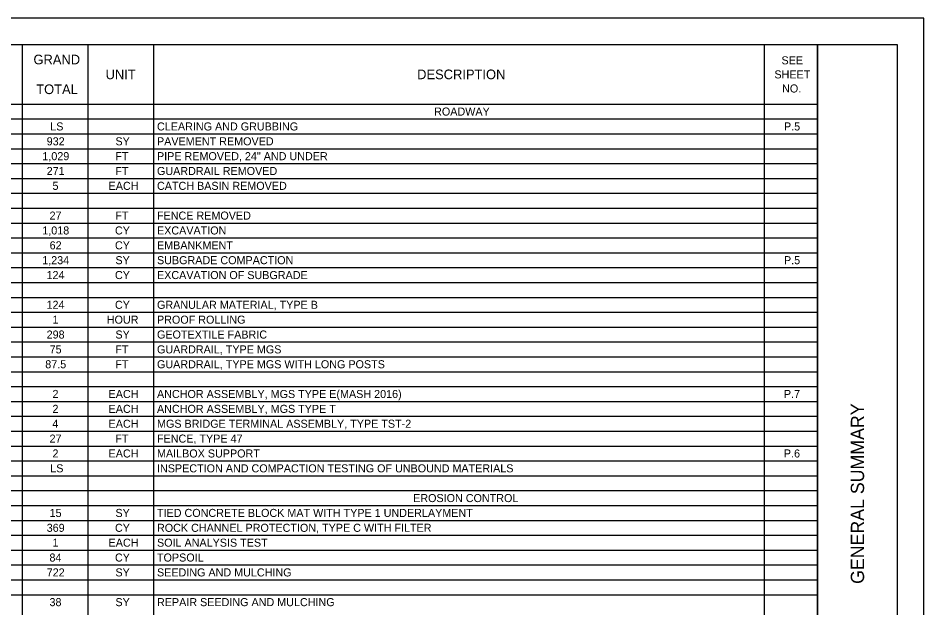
# Model space of a CAD drawing. Extents: x 0 to 34, y 0 to 22.
# Drawn here: x 16.95 to 34, y 10.89 to 22 of the extents above; entities that cross this region are included whole.
import ezdxf

# ---------------------------------------------------------------- set-up
doc = ezdxf.new("R2010")
doc.units = 0
for name, color, linetype in [('Default', 7, 'Continuous'), ('SH_Border', 7, 'Continuous'), ('SH_Cut_Line', 7, 'Continuous'), ('SH_Data', 7, 'Continuous')]:
    doc.layers.add(name, color=color, linetype=linetype)

msp = doc.modelspace()

# ---------------------------------------------------------------- linework, layer by layer
at = {"layer": 'Default'}
for p, q in [((1.5, 21.5), (32, 21.5)), ((17.03, 21.5), (17.03, 0.502)), ((18.265, 21.5), (18.265, 0.502)), ((19.5, 21.5), (19.5, 0.502)), ((30.995, 21.5), (30.995, 0.502)), ((32, 21.5), (32, 0.502)), ((1.5, 20.38), (32, 20.38)), ((1.5, 20.1), (32, 20.1)), ((1.5, 19.82), (32, 19.82)), ((1.5, 19.54), (32, 19.54)), ((1.5, 19.26), (32, 19.26)), ((1.5, 18.98), (32, 18.98)), ((1.5, 18.7), (32, 18.7)), ((1.5, 18.42), (32, 18.42)), ((1.5, 18.14), (32, 18.14)), ((1.5, 17.86), (32, 17.86)), ((1.5, 17.58), (32, 17.58)), ((1.5, 17.3), (32, 17.3)), ((1.5, 17.021), (32, 17.021)), ((1.5, 16.741), (32, 16.741)), ((1.5, 16.461), (32, 16.461)), ((1.5, 16.181), (32, 16.181)), ((1.5, 15.901), (32, 15.901)), ((1.5, 15.621), (32, 15.621)), ((1.5, 15.341), (32, 15.341)), ((1.5, 15.061), (32, 15.061)), ((1.5, 14.781), (32, 14.781)), ((1.5, 14.501), (32, 14.501)), ((1.5, 14.221), (32, 14.221)), ((1.5, 13.941), (32, 13.941)), ((1.5, 13.661), (32, 13.661)), ((1.5, 13.381), (32, 13.381)), ((1.5, 13.101), (32, 13.101)), ((1.5, 12.821), (32, 12.821)), ((1.5, 12.541), (32, 12.541)), ((1.5, 12.261), (32, 12.261)), ((1.5, 11.981), (32, 11.981)), ((1.5, 11.701), (32, 11.701)), ((1.5, 11.421), (32, 11.421)), ((1.5, 11.141), (32, 11.141))]:
    msp.add_line(p, q, dxfattribs=at)
at = {"layer": 'SH_Border'}
msp.add_line((32, 0.5), (32, 21.5), dxfattribs=at)
msp.add_lwpolyline([(1.5, 21.5), (33.5, 21.5), (33.5, 0.5), (1.5, 0.5)], close=True, dxfattribs=at)
at = {"layer": 'SH_Cut_Line'}
msp.add_lwpolyline([(0, 0), (34, 0), (34, 22), (0, 22)], close=True, dxfattribs=at)

# ---------------------------------------------------------------- texts
at = {"layer": 'Default'}
for s, height, p in [('GRAND', 0.1818, (17.241, 21.129)), ('SEE ', 0.1515, (31.32, 21.129)), ('UNIT', 0.1818, (18.599, 20.849)), ('DESCRIPTION', 0.18181, (24.462, 20.849)), ('SHEET ', 0.1515, (31.187, 20.864)), ('TOTAL', 0.1818, (17.293, 20.569)), ('NO.', 0.1515, (31.331, 20.599)), ('ROADWAY', 0.1515, (24.782, 20.164)), ('LS', 0.1515, (17.557, 19.884)), ('CLEARING AND GRUBBING', 0.15151, (19.566, 19.884)), ('P.5', 0.1515, (31.367, 19.884)), ('932', 0.1515, (17.49, 19.604)), ('SY', 0.1515, (18.784, 19.604)), ('PAVEMENT REMOVED', 0.15151, (19.566, 19.604)), ('1,029', 0.1515, (17.408, 19.324)), ('FT', 0.1515, (18.782, 19.324)), ('PIPE REMOVED, 24" AND UNDER', 0.15151, (19.566, 19.324)), ('271', 0.1515, (17.49, 19.045)), ('FT', 0.1515, (18.782, 19.045)), ('GUARDRAIL REMOVED', 0.15151, (19.566, 19.045)), ('5', 0.152, (17.599, 18.765)), ('EACH', 0.1515, (18.655, 18.765)), ('CATCH BASIN REMOVED', 0.15151, (19.566, 18.765)), ('27', 0.1515, (17.544, 18.205)), ('FT', 0.1515, (18.782, 18.205)), ('FENCE REMOVED', 0.15151, (19.566, 18.205)), ('1,018', 0.1515, (17.407, 17.925)), ('CY', 0.1515, (18.775, 17.925)), ('EXCAVATION', 0.1515, (19.566, 17.925)), ('62', 0.1515, (17.545, 17.645)), ('CY', 0.1515, (18.775, 17.645)), ('EMBANKMENT', 0.1515, (19.566, 17.645)), ('1,234', 0.1515, (17.406, 17.365)), ('SY', 0.1515, (18.784, 17.365)), ('SUBGRADE COMPACTION', 0.15151, (19.566, 17.365)), ('P.5', 0.1515, (31.367, 17.365)), ('124', 0.1515, (17.487, 17.085)), ('CY', 0.1515, (18.775, 17.085)), ('EXCAVATION OF SUBGRADE', 0.15151, (19.566, 17.085)), ('124', 0.1515, (17.487, 16.525)), ('CY', 0.1515, (18.775, 16.525)), ('GRANULAR MATERIAL, TYPE B', 0.15151, (19.566, 16.525)), ('1', 0.152, (17.599, 16.245)), ('HOUR', 0.1515, (18.621, 16.245)), ('PROOF ROLLING', 0.15151, (19.566, 16.245)), ('298', 0.1515, (17.489, 15.965)), ('SY', 0.1515, (18.784, 15.965)), ('GEOTEXTILE FABRIC', 0.15151, (19.566, 15.965)), ('75', 0.1515, (17.545, 15.685)), ('FT', 0.1515, (18.782, 15.685)), ('GUARDRAIL, TYPE MGS', 0.15151, (19.566, 15.685)), ('87.5', 0.1515, (17.463, 15.405)), ('FT', 0.1515, (18.782, 15.405)), ('GUARDRAIL, TYPE MGS WITH LONG POSTS', 0.15151, (19.566, 15.405)), ('ANCHOR ASSEMBLY, MGS TYPE E(MASH 2016)', 0.15151, (19.566, 14.845)), ('2', 0.152, (17.599, 14.845)), ('EACH', 0.1515, (18.655, 14.845)), ('P.7', 0.1515, (31.366, 14.845)), ('2', 0.152, (17.599, 14.565)), ('EACH', 0.1515, (18.655, 14.565)), ('ANCHOR ASSEMBLY, MGS TYPE T', 0.15151, (19.566, 14.565)), ('4', 0.152, (17.596, 14.285)), ('EACH', 0.1515, (18.655, 14.285)), ('MGS BRIDGE TERMINAL ASSEMBLY, TYPE TST-2', 0.15151, (19.566, 14.285)), ('27', 0.1515, (17.544, 14.005)), ('FT', 0.1515, (18.782, 14.005)), ('FENCE, TYPE 47', 0.15151, (19.566, 14.005)), ('2', 0.152, (17.599, 13.725)), ('EACH', 0.1515, (18.655, 13.725)), ('MAILBOX SUPPORT', 0.15151, (19.566, 13.725)), ('P.6', 0.1515, (31.365, 13.725)), ('LS', 0.1515, (17.557, 13.445)), ('INSPECTION AND COMPACTION TESTING OF UNBOUND MATERIALS', 0.15151, (19.566, 13.445)), ('EROSION CONTROL', 0.15151, (24.387, 12.885)), ('15', 0.1515, (17.545, 12.605)), ('SY', 0.1515, (18.784, 12.605)), ('TIED CONCRETE BLOCK MAT WITH TYPE 1 UNDERLAYMENT', 0.15151, (19.566, 12.605)), ('369', 0.1515, (17.49, 12.325)), ('CY', 0.1515, (18.775, 12.325)), ('ROCK CHANNEL PROTECTION, TYPE C WITH FILTER', 0.15151, (19.566, 12.325)), ('1', 0.152, (17.599, 12.045)), ('EACH', 0.1515, (18.655, 12.045)), ('SOIL ANALYSIS TEST', 0.15151, (19.566, 12.045)), ('84', 0.1515, (17.542, 11.765)), ('CY', 0.1515, (18.775, 11.765)), ('TOPSOIL', 0.1515, (19.566, 11.765)), ('722', 0.1515, (17.49, 11.485)), ('SY', 0.1515, (18.784, 11.485)), ('SEEDING AND MULCHING', 0.15151, (19.566, 11.485)), ('38', 0.1515, (17.543, 10.925)), ('SY', 0.1515, (18.784, 10.925)), ('REPAIR SEEDING AND MULCHING', 0.15151, (19.566, 10.925))]:
    msp.add_text(s, height=height, dxfattribs=at).set_placement(p)
at = {"layer": 'SH_Data'}
msp.add_text('GENERAL SUMMARY', height=0.25, rotation=90, dxfattribs=at).set_placement((32.875, 11.344))

doc.saveas('drawing.dxf')
